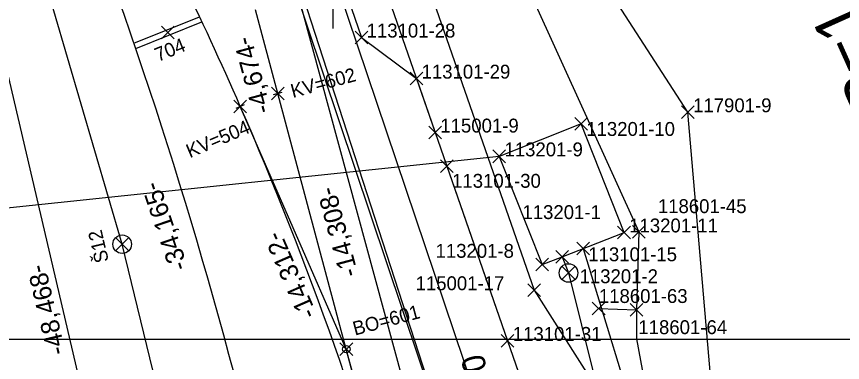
# Model space of a CAD drawing. Extents: x -821029 to -820632, y -1070881 to -1069931.
# Drawn here: x -820817.11 to -820772.47, y -1070419.3 to -1070400.61 of the extents above; entities that cross this region are included whole.
import ezdxf

# ---------------------------------------------------------------- set-up
doc = ezdxf.new("R2010")
doc.units = 0
for name, color, linetype in [('_PS_SO_číslo', 7, 'Continuous'), ('PS-11-02-31', 7, 'Continuous'), ('PS-11-02-41', 7, 'Continuous'), ('PS-11-02-92', 7, 'Continuous'), ('Sit', 7, 'Continuous'), ('SO-11-10-01', 7, 'Continuous'), ('SO-11-31-01', 7, 'Continuous'), ('SO-11-32-01', 7, 'Continuous'), ('SO-11-50-01', 7, 'Continuous'), ('SO-11-79-01', 7, 'Continuous'), ('SO-11-86-01', 7, 'Continuous'), ('VB_SO-11-10-01', 7, 'Continuous'), ('VB_SO-11-31-01', 7, 'Continuous'), ('VB_SO-11-32-01', 7, 'Continuous'), ('VB_SO-11-50-01', 7, 'Continuous'), ('VB_SO-11-79-01', 7, 'Continuous'), ('VB_SO-11-86-01', 7, 'Continuous')]:
    doc.layers.add(name, color=color, linetype=linetype)

msp = doc.modelspace()

# ---------------------------------------------------------------- linework, layer by layer
at = {"layer": '_PS_SO_číslo'}
msp.add_line((-820791.02, -1070408.16), (-820852.097, -1070414.6), dxfattribs=at)
msp.add_lwpolyline([(-820818.962, -1070418.04), (-820767.714, -1070418.04), (-820767.714, -1070447.591), (-820818.962, -1070447.591)], close=True, dxfattribs=at)
at = {"layer": 'PS-11-02-31'}
for points in [[(-820959.278, -1070122.218), (-820934.84, -1070144.095), (-820933.002, -1070146.602), (-820925.146, -1070161.738), (-820918.63, -1070175.611), (-820911.367, -1070188.874), (-820902.582, -1070186.65), (-820896.686, -1070196.978), (-820870.459, -1070236.453), (-820846.568, -1070277.079), (-820842.598, -1070282.108), (-820813.472, -1070365.169), (-820809.802, -1070374.33), (-820792.803, -1070426.722), (-820792.342, -1070428.474), (-820790.079, -1070430.856), (-820788.925, -1070435.581), (-820780.392, -1070470.858), (-820770.551, -1070511.609), (-820767.886, -1070524.681), (-820765.297, -1070562.399), (-820759.609, -1070562.181)], [(-820834.739, -1070280.72), (-820830.77, -1070287.401), (-820826.598, -1070295.778), (-820822.74, -1070307.417), (-820822.402, -1070310.542), (-820820.817, -1070316.363), (-820815.079, -1070335.816), (-820806.043, -1070362.212), (-820801.047, -1070374.777), (-820795.979, -1070387.28), (-820794.84, -1070387.997), (-820792.153, -1070393.193), (-820783.482, -1070412.233), (-820783.598, -1070416.458), (-820783.598, -1070418.019), (-820782.431, -1070424.351)]]:
    msp.add_lwpolyline(points, dxfattribs=at)
at = {"layer": 'PS-11-02-41'}
msp.add_lwpolyline([(-820882.988, -1070201.129), (-820875.537, -1070207.75), (-820872.787, -1070212.312), (-820866.572, -1070222.102), (-820863.695, -1070232.226), (-820854.155, -1070247.197), (-820844.785, -1070263.708), (-820834.739, -1070280.72), (-820830.77, -1070287.401), (-820826.598, -1070295.778), (-820822.74, -1070307.417), (-820822.402, -1070310.542), (-820820.817, -1070316.363), (-820815.079, -1070335.816), (-820806.043, -1070362.212), (-820801.047, -1070374.777), (-820795.979, -1070387.28), (-820794.84, -1070387.997), (-820792.153, -1070393.193), (-820783.482, -1070412.233), (-820783.598, -1070416.458), (-820783.598, -1070418.019), (-820782.431, -1070424.351)], dxfattribs=at)
at = {"layer": 'PS-11-02-92'}
msp.add_lwpolyline([(-820882.988, -1070201.129), (-820875.537, -1070207.75), (-820872.787, -1070212.312), (-820866.572, -1070222.102), (-820863.695, -1070232.226), (-820854.155, -1070247.197), (-820844.785, -1070263.708), (-820834.739, -1070280.72), (-820830.77, -1070287.401), (-820826.598, -1070295.778), (-820822.74, -1070307.417), (-820822.402, -1070310.542), (-820820.817, -1070316.363), (-820815.079, -1070335.816), (-820806.043, -1070362.212), (-820801.047, -1070374.777), (-820795.979, -1070387.28), (-820794.84, -1070387.997), (-820792.153, -1070393.193), (-820783.482, -1070412.233), (-820783.598, -1070416.458), (-820783.598, -1070418.019), (-820782.431, -1070424.351)], dxfattribs=at)
at = {"layer": 'Sit'}
msp.add_line((-820800, -1070401.25), (-820800, -1070400), dxfattribs=at)
at = {"layer": 'SO-11-10-01'}
for p, q in [((-820802.989, -1070404.758), (-820804.198, -1070400.243)), ((-820810.769, -1070402.054), (-820807.22, -1070400.618)), ((-820810.67, -1070402.338), (-820807.094, -1070400.89)), ((-820808.931, -1070401.472), (-820808.931, -1070401.472)), ((-820803.23, -1070404.823), (-820802.748, -1070404.693)), ((-820799.288, -1070418.579), (-820802.989, -1070404.758)), ((-820805.248, -1070405.565), (-820804.79, -1070405.365)), ((-820799.288, -1070418.579), (-820805.019, -1070405.465)), ((-820799.288, -1070418.579), (-820805.019, -1070405.465)), ((-820795.796, -1070431.621), (-820799.288, -1070418.579))]:
    msp.add_line(p, q, dxfattribs=at)
for points in [[(-820791.836, -1070436.403), (-820804.578, -1070389.555), (-820809.286, -1070391.234), (-820814.195, -1070381.747)], [(-820804.905, -1070439.605), (-820811.403, -1070412.909), (-820819.538, -1070385.143)], [(-820761.019, -1070645.411), (-820786.886, -1070534.867), (-820787.456, -1070532.433), (-820788.025, -1070529.999), (-820808.595, -1070442.095), (-820809.131, -1070439.803), (-820809.668, -1070437.51), (-820820.711, -1070390.317)], [(-820795.586, -1070432.404), (-820799.288, -1070418.579), (-820802.989, -1070404.758)]]:
    msp.add_lwpolyline(points, dxfattribs=at)
for centre, radius in [((-820811.403, -1070412.909), 0.5), ((-820799.288, -1070418.579), 0.2)]:
    msp.add_circle(centre, radius, dxfattribs=at)
for centre, major_axis, ratio, start_param, end_param in [((-820979.107, -1070481.534), (-110.746, 154.387), 0.9999, 4.502101, 4.583959), ((-821056.703, -1070486.397), (38.305, 257.163), 0.999985, 5.090175, 5.221577), ((-820979.113, -1070481.557), (-128.262, 140.174), 0.999982, 4.237298, 4.383398)]:
    msp.add_ellipse(centre, major_axis=major_axis, ratio=ratio, start_param=start_param, end_param=end_param, dxfattribs=at)
at = {"layer": 'SO-11-31-01'}
msp.add_line((-820786.49, -1070413.14), (-820781.3, -1070430.05), dxfattribs=at)
for points in [[(-820926.07, -1070123.29), (-820916.95, -1070167.12), (-820908.61, -1070171.6), (-820902.99, -1070184.31), (-820895.92, -1070196.33), (-820868.5, -1070237.37), (-820845.66, -1070276.46), (-820841.66, -1070281.51), (-820839.82, -1070285.2), (-820808.13, -1070374.18), (-820790.33, -1070426.97), (-820782.93, -1070433.41), (-820769.19, -1070488.5), (-820779.762, -1070491.365)], [(-820832.57, -1070337.97), (-820821.56, -1070335.44), (-820813.99, -1070356.68), (-820798.47, -1070401.74), (-820795.5, -1070403.96), (-820793.85, -1070408.69), (-820790.57, -1070418.13), (-820788.93, -1070422.85), (-820783.27, -1070428.36), (-820780.97, -1070427.76), (-820780.24, -1070428.17), (-820779.88, -1070429.72), (-820781.01, -1070429.99)]]:
    msp.add_lwpolyline(points, dxfattribs=at)
at = {"layer": 'SO-11-32-01'}
msp.add_lwpolyline([(-820788.7, -1070414.01), (-820787.62, -1070413.59), (-820784.28, -1070412.27), (-820786.6, -1070406.41), (-820791.02, -1070408.16)], close=True, dxfattribs=at)
msp.add_lwpolyline([(-820787.62, -1070413.59), (-820787.28, -1070414.46), (-820762.46, -1070514.35), (-820773.88, -1070517.14)], dxfattribs=at)
msp.add_circle((-820787.28, -1070414.46), 0.5, dxfattribs=at)
at = {"layer": 'SO-11-50-01'}
for points in [[(-820831.742, -1070299.721), (-820794.486, -1070406.873), (-820788.19, -1070424.98)], [(-820815.774, -1070338.796), (-820798.172, -1070389.423), (-820789.142, -1070415.392), (-820782.756, -1070425.414), (-820778.113, -1070440.812), (-820778.3, -1070451.359), (-820766.965, -1070499.852)]]:
    msp.add_lwpolyline(points, dxfattribs=at)
at = {"layer": 'SO-11-79-01'}
msp.add_lwpolyline([(-820761.036, -1070511.475), (-820774.105, -1070459.005), (-820777.683, -1070442.395), (-820780.824, -1070405.778), (-820791.175, -1070389.775), (-820795.413, -1070386.908), (-820807.598, -1070359.392), (-820815.489, -1070325.838), (-820825.29, -1070295.054), (-820830.464, -1070283.216), (-820832.859, -1070278.435)], dxfattribs=at)
at = {"layer": 'SO-11-86-01'}
msp.add_line((-820785.65, -1070416.385), (-820783.598, -1070416.458), dxfattribs=at)
for points in [[(-820870.459, -1070236.454), (-820846.568, -1070277.079), (-820842.598, -1070282.108), (-820813.472, -1070365.169), (-820792.803, -1070426.722), (-820792.342, -1070428.474), (-820790.079, -1070430.857), (-820788.924, -1070435.581), (-820780.392, -1070470.858), (-820770.551, -1070511.609), (-820767.886, -1070524.681), (-820765.297, -1070562.4), (-820759.609, -1070562.181), (-820765.131, -1070563.533), (-820782.387, -1070567.755), (-820781.928, -1070569.717), (-820782.387, -1070567.755)], [(-820844.785, -1070263.708), (-820834.739, -1070280.72), (-820830.77, -1070287.401), (-820826.598, -1070295.778), (-820822.74, -1070307.417), (-820822.402, -1070310.542), (-820820.817, -1070316.363), (-820815.079, -1070335.816), (-820806.043, -1070362.212), (-820801.047, -1070374.777), (-820795.979, -1070387.28), (-820794.84, -1070387.997), (-820792.153, -1070393.193), (-820783.482, -1070412.233), (-820783.598, -1070416.458), (-820783.598, -1070418.019), (-820782.431, -1070424.351), (-820780.96, -1070434.384), (-820773.909, -1070463.726), (-820769.347, -1070482.633)]]:
    msp.add_lwpolyline(points, dxfattribs=at)
at = {"layer": 'VB_SO-11-10-01'}
for p, q in [((-820809.275, -1070401.816), (-820808.587, -1070401.128)), ((-820808.587, -1070401.816), (-820809.275, -1070401.128)), ((-820803.333, -1070405.102), (-820802.645, -1070404.414)), ((-820802.645, -1070405.102), (-820803.333, -1070404.414)), ((-820805.363, -1070405.808), (-820804.676, -1070405.121)), ((-820804.676, -1070405.808), (-820805.363, -1070405.121)), ((-820811.747, -1070413.253), (-820811.059, -1070412.565)), ((-820811.059, -1070413.253), (-820811.747, -1070412.565)), ((-820799.632, -1070418.923), (-820798.944, -1070418.235)), ((-820798.944, -1070418.923), (-820799.632, -1070418.235))]:
    msp.add_line(p, q, dxfattribs=at)
at = {"layer": 'VB_SO-11-31-01'}
for p, q in [((-820798.814, -1070402.084), (-820798.126, -1070401.396)), ((-820798.126, -1070402.084), (-820798.814, -1070401.396)), ((-820795.844, -1070404.304), (-820795.156, -1070403.616)), ((-820795.156, -1070404.304), (-820795.844, -1070403.616)), ((-820794.194, -1070409.034), (-820793.506, -1070408.346)), ((-820793.506, -1070409.034), (-820794.194, -1070408.346)), ((-820786.834, -1070413.484), (-820786.146, -1070412.796)), ((-820786.146, -1070413.484), (-820786.834, -1070412.796)), ((-820790.914, -1070418.474), (-820790.226, -1070417.786)), ((-820790.226, -1070418.474), (-820790.914, -1070417.786))]:
    msp.add_line(p, q, dxfattribs=at)
at = {"layer": 'VB_SO-11-32-01'}
for p, q in [((-820786.944, -1070406.754), (-820786.256, -1070406.066)), ((-820786.256, -1070406.754), (-820786.944, -1070406.066)), ((-820791.364, -1070408.504), (-820790.676, -1070407.816)), ((-820790.676, -1070408.504), (-820791.364, -1070407.816)), ((-820784.624, -1070412.614), (-820783.936, -1070411.926)), ((-820783.936, -1070412.614), (-820784.624, -1070411.926)), ((-820787.964, -1070413.934), (-820787.276, -1070413.246)), ((-820787.276, -1070413.934), (-820787.964, -1070413.246)), ((-820789.044, -1070414.354), (-820788.356, -1070413.666)), ((-820788.356, -1070414.354), (-820789.044, -1070413.666)), ((-820787.624, -1070414.804), (-820786.936, -1070414.116)), ((-820786.936, -1070414.804), (-820787.624, -1070414.116))]:
    msp.add_line(p, q, dxfattribs=at)
at = {"layer": 'VB_SO-11-50-01'}
for p, q in [((-820794.83, -1070407.217), (-820794.142, -1070406.529)), ((-820794.142, -1070407.217), (-820794.83, -1070406.529)), ((-820789.486, -1070415.736), (-820788.798, -1070415.048)), ((-820788.798, -1070415.736), (-820789.486, -1070415.048))]:
    msp.add_line(p, q, dxfattribs=at)
at = {"layer": 'VB_SO-11-79-01'}
for p, q in [((-820781.168, -1070406.122), (-820780.48, -1070405.434)), ((-820780.48, -1070406.122), (-820781.168, -1070405.434))]:
    msp.add_line(p, q, dxfattribs=at)
at = {"layer": 'VB_SO-11-86-01'}
for p, q in [((-820783.826, -1070412.577), (-820783.138, -1070411.889)), ((-820783.138, -1070412.577), (-820783.826, -1070411.889)), ((-820785.994, -1070416.729), (-820785.306, -1070416.041)), ((-820785.306, -1070416.729), (-820785.994, -1070416.041)), ((-820783.942, -1070416.802), (-820783.254, -1070416.114)), ((-820783.254, -1070416.802), (-820783.942, -1070416.114))]:
    msp.add_line(p, q, dxfattribs=at)

# ---------------------------------------------------------------- texts
at = {"layer": 'SO-11-10-01'}
for s, height, rotation, p in [('V=40km/h; D=0mm; l=100mm; alfas=16,803876g; Li,o=50,151m', 0.75, 114.1933, (-820764.491, -1070410.46)), ('R=190 m', 2.5, 114.1933, (-820769.432, -1070405.179)), ('-4,674-', 1, 104.9906, (-820803.347, -1070405.71)), ('-34,165-', 1, 108.7009, (-820807.836, -1070414.159)), ('-14,308-', 1, 104.991, (-820798.633, -1070414.544)), ('-14,312-', 1, 113.606, (-820800.86, -1070416.689)), ('-48,468-', 1, 103.1701, (-820814.447, -1070418.782)), ('J49-1:6,6-190', 1.25, 103.7999, (-820789.438, -1070428.785))]:
    msp.add_text(s, height=height, rotation=rotation, dxfattribs=at).set_placement(p)
at = {"layer": 'VB_SO-11-10-01'}
for s, rotation, p in [('704', 22.0331, (-820809.459, -1070403.062)), ('KV=602', 14.991, (-820802.179, -1070405.01)), ('KV=504', 22.8806, (-820807.749, -1070408.263)), ('Š12', 103.1701, (-820812.119, -1070413.816)), ('BO=601', 14.9907, (-820798.824, -1070417.847))]:
    msp.add_text(s, height=0.75, rotation=rotation, dxfattribs=at).set_placement(p)
at = {"layer": 'VB_SO-11-31-01'}
for s, p in [(' 113101-28', (-820798.47, -1070401.74)), (' 113101-29', (-820795.5, -1070403.96)), (' 113101-30', (-820793.85, -1070409.858)), (' 113101-15', (-820786.49, -1070413.827)), (' 113101-31', (-820790.57, -1070418.13))]:
    msp.add_text(s, height=0.75, dxfattribs=at).set_placement(p)
at = {"layer": 'VB_SO-11-32-01'}
for s, p in [(' 113201-10', (-820786.6, -1070407.055)), (' 113201-9', (-820791.02, -1070408.16)), (' 113201-1', (-820790.048, -1070411.548)), (' 113201-11', (-820784.28, -1070412.27)), (' 113201-8', (-820794.746, -1070413.641)), (' 113201-2', (-820786.962, -1070415.013))]:
    msp.add_text(s, height=0.75, dxfattribs=at).set_placement(p)
at = {"layer": 'VB_SO-11-50-01'}
for s, p in [(' 115001-9', (-820794.486, -1070406.873)), (' 115001-17', (-820795.824, -1070415.392))]:
    msp.add_text(s, height=0.75, dxfattribs=at).set_placement(p)
at = {"layer": 'VB_SO-11-79-01'}
msp.add_text(' 117901-9', height=0.75, dxfattribs=at).set_placement((-820780.824, -1070405.778))
at = {"layer": 'VB_SO-11-86-01'}
for s, p in [(' 118601-45', (-820782.728, -1070411.227)), (' 118601-63', (-820785.918, -1070416.083)), (' 118601-64', (-820783.782, -1070417.766))]:
    msp.add_text(s, height=0.75, dxfattribs=at).set_placement(p)

doc.saveas('drawing.dxf')
